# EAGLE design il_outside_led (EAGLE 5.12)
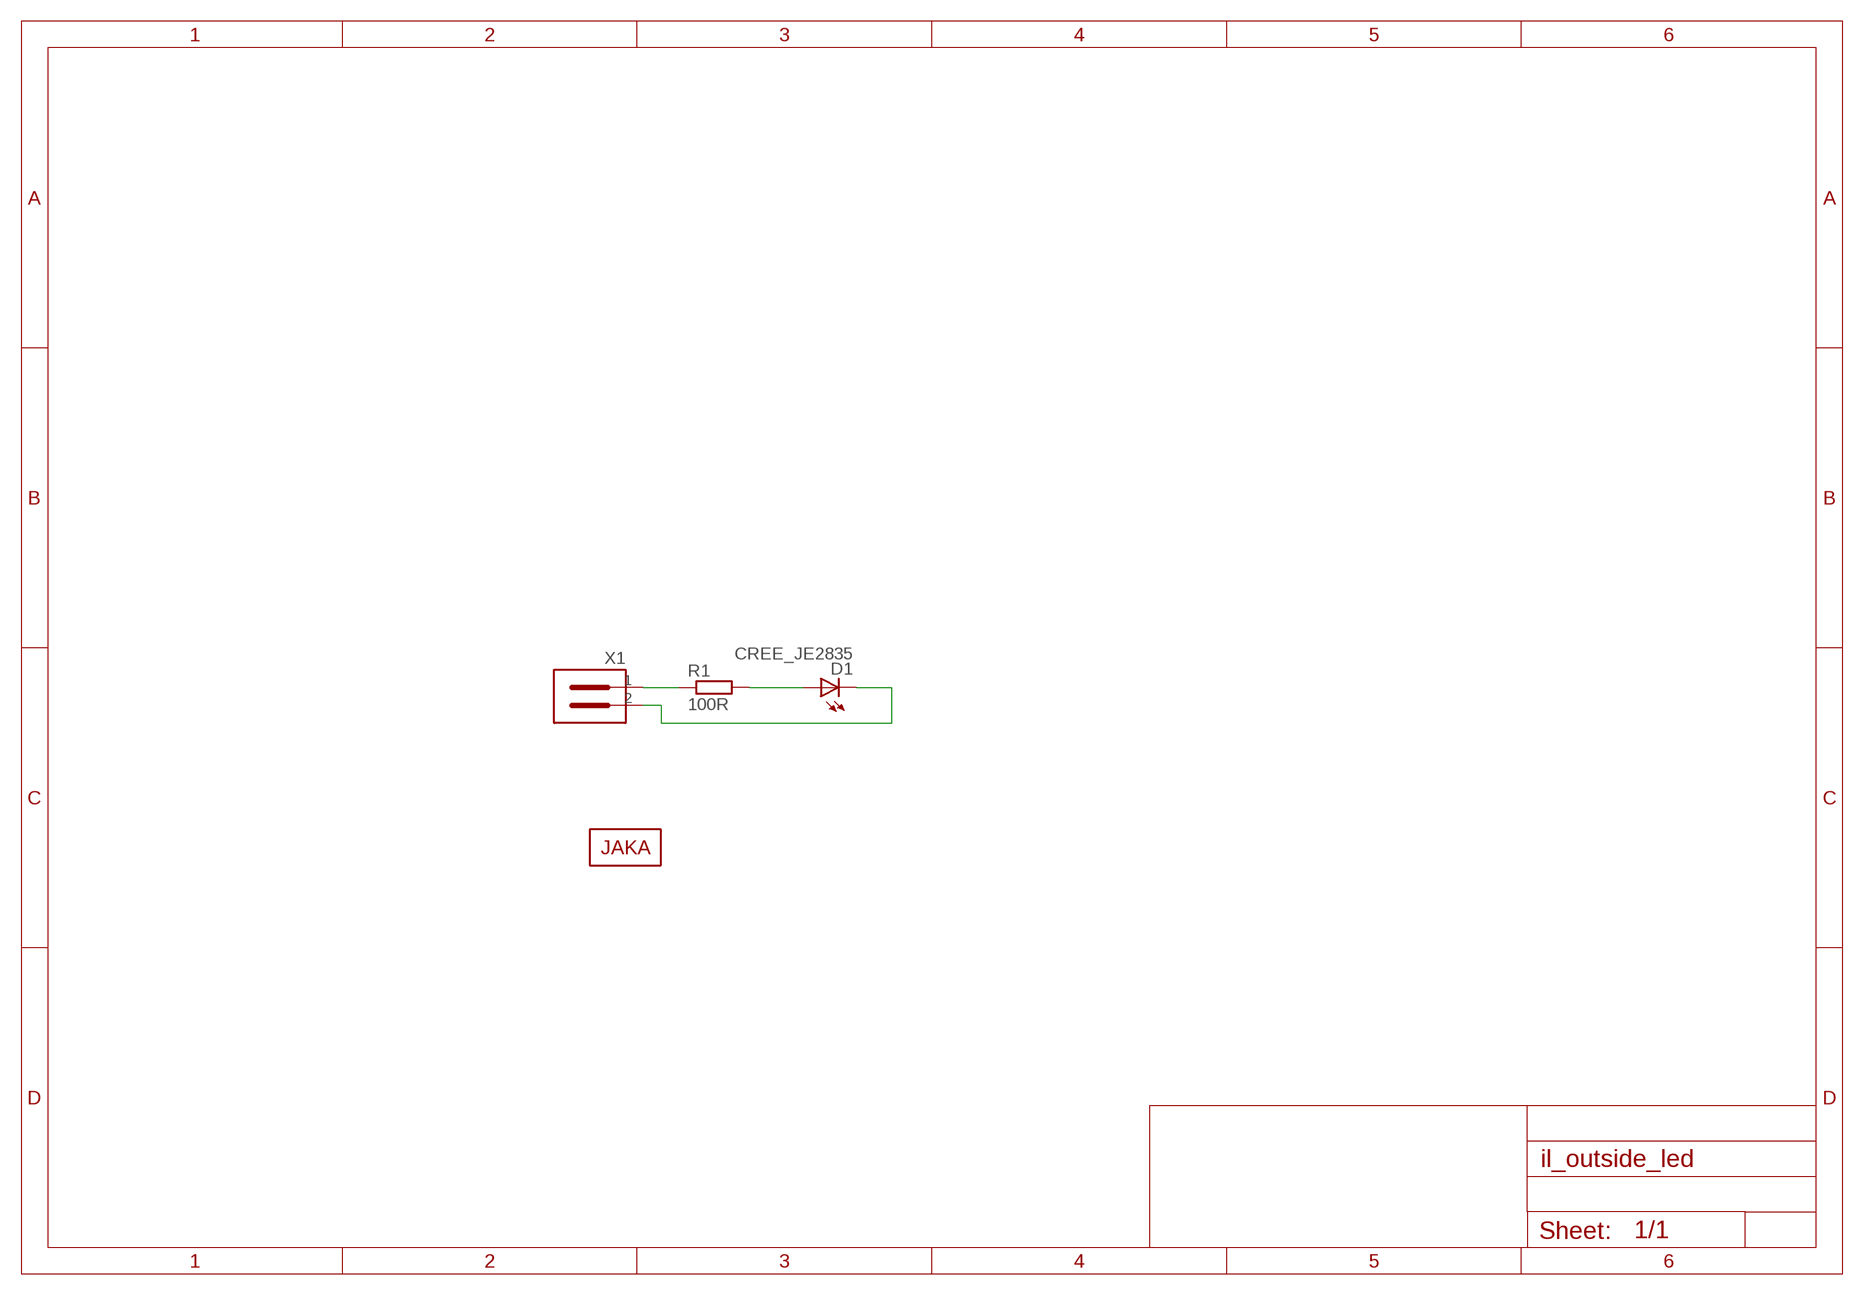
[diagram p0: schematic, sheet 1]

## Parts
D1  CREE_JE2835  [CREE_J2835]
R1  100R  R-EU_R0805  [R0805]
U$1  JAKA_LOGO_SILK_NANO  [JAKA_SILK_NANO]
X1  B2B-XH-A(LF)(SN)  [B2B-XH-A]

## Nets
N$1: R1.1 X1.1
N$2: D1.A R1.2
N$3: D1.K X1.2

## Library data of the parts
D1 = omat:CREE_JE2835
R1 = omat:R-EU_: RESISTOR, European symbol
U$1 = omat:JAKA_LOGO
X1 = omat:B2B-XH-A(LF)(SN)

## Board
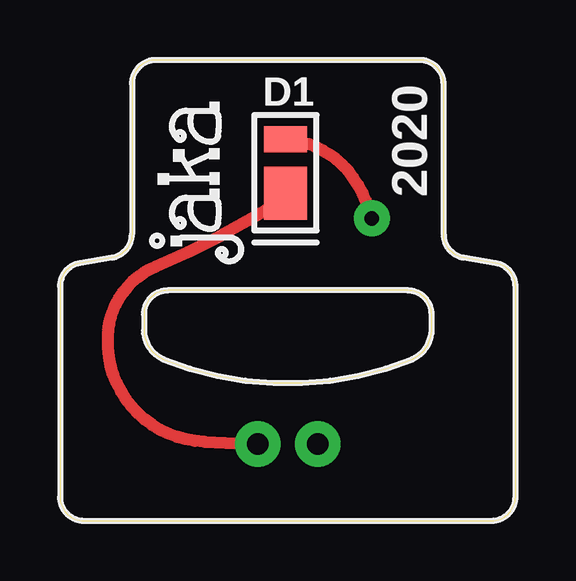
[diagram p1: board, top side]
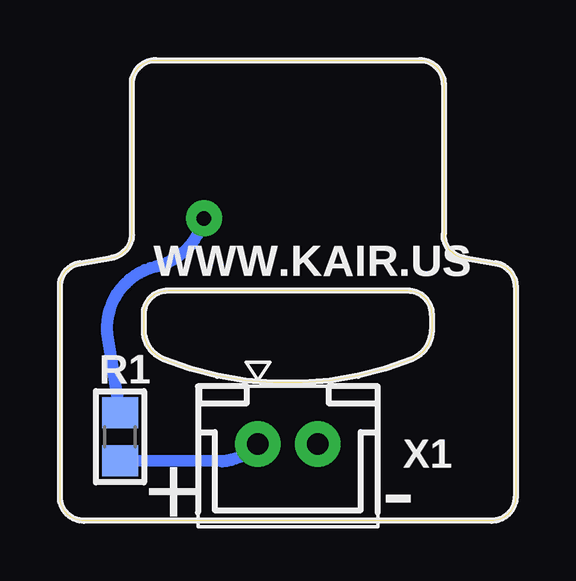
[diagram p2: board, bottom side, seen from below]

Size 19 x 19.2 mm. Coordinates in mm from the lower left corner, seen from the top.
Outline: 19,9.75 arc81 18.16,10.74 16.84,10.96 arc-81 16,11.95 16,18.2 arc90 15,19.2 4,19.2 arc90 3,18.2 3,11.95 arc-81 2.16,10.96 0.84,10.74 arc81 0,9.75 0,1 arc90 1,0 18,0 arc90 19,1 19,9.75
Outline: 14.7,6.74 arc65 15.5,7.92 15.5,8.6 arc90 14.5,9.6 4.5,9.6 arc90 3.5,8.6 3.5,7.92 arc65 4.3,6.74 arc44 14.7,6.74
Copper layers (1*16): Top 0.035mm / dielectric 1.5mm / Bottom 0.035mm
Design rules "default": minimum track width 10mil, minimum drill 24mil, track to track 8mil, track to pad 8mil, pad to pad 8mil, via to via 8mil, smd to smd 8mil, copper to edge 40mil, drill to drill 8mil, minimum pad ring 10mil, minimum via ring 8mil, stop-mask expansion 4mil, vias tented up to drill 0mil, thermal gap 10mil

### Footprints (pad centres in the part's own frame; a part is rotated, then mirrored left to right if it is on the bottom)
CREE_J2835 = smd 1.1 x 1.8: A 1.4,0 | smd 2.2 x 1.8: K -0.85,0
R0805 = smd 1.3 x 1.5: 1 -1,0; 2 1,0
B2B-XH-A = drill 0.9 pad 1.9 round: 1 -1.25,0; 2 1.25,0

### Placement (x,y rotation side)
D1  9.4,14.5 90 top
R1  16.5,3.5 90 bottom
U$1  5.7,14.1 90 top
X1  9.5,3.2 0 bottom

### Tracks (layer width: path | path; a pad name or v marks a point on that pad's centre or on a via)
N$1
  Bottom 0.5: R1.1 12.23,2.48 arc-45 X1.1
N$2  (via drill 0.6 pad 1.5)
  Top 0.5: v13,12.6 arc26 12,14.6 arc44 D1.A
  Bottom 0.5: R1.2 17,7.6 arc86 15,10.6 arc-63 v13,12.6
N$3
  Top 0.5: D1.K arc-18 8,12.6 arc-8 4,10.6 arc67 2,7.6 arc90 6,3.3 X1.2

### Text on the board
tPlace: 2020
bPlace: WWW.KAIR.US | - | +
bStop: iL | outside | LED
_tsilk: D1 | 2020
_bsilk: WWW.KAIR.US | R1 | X1 | - | +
